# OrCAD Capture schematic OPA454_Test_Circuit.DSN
size A; title: OPA454 High-Voltage (100V), High-Current (50mA); rev: 1.1; note: Datasheet:SBOS391B EVM: N/A; note: Reference
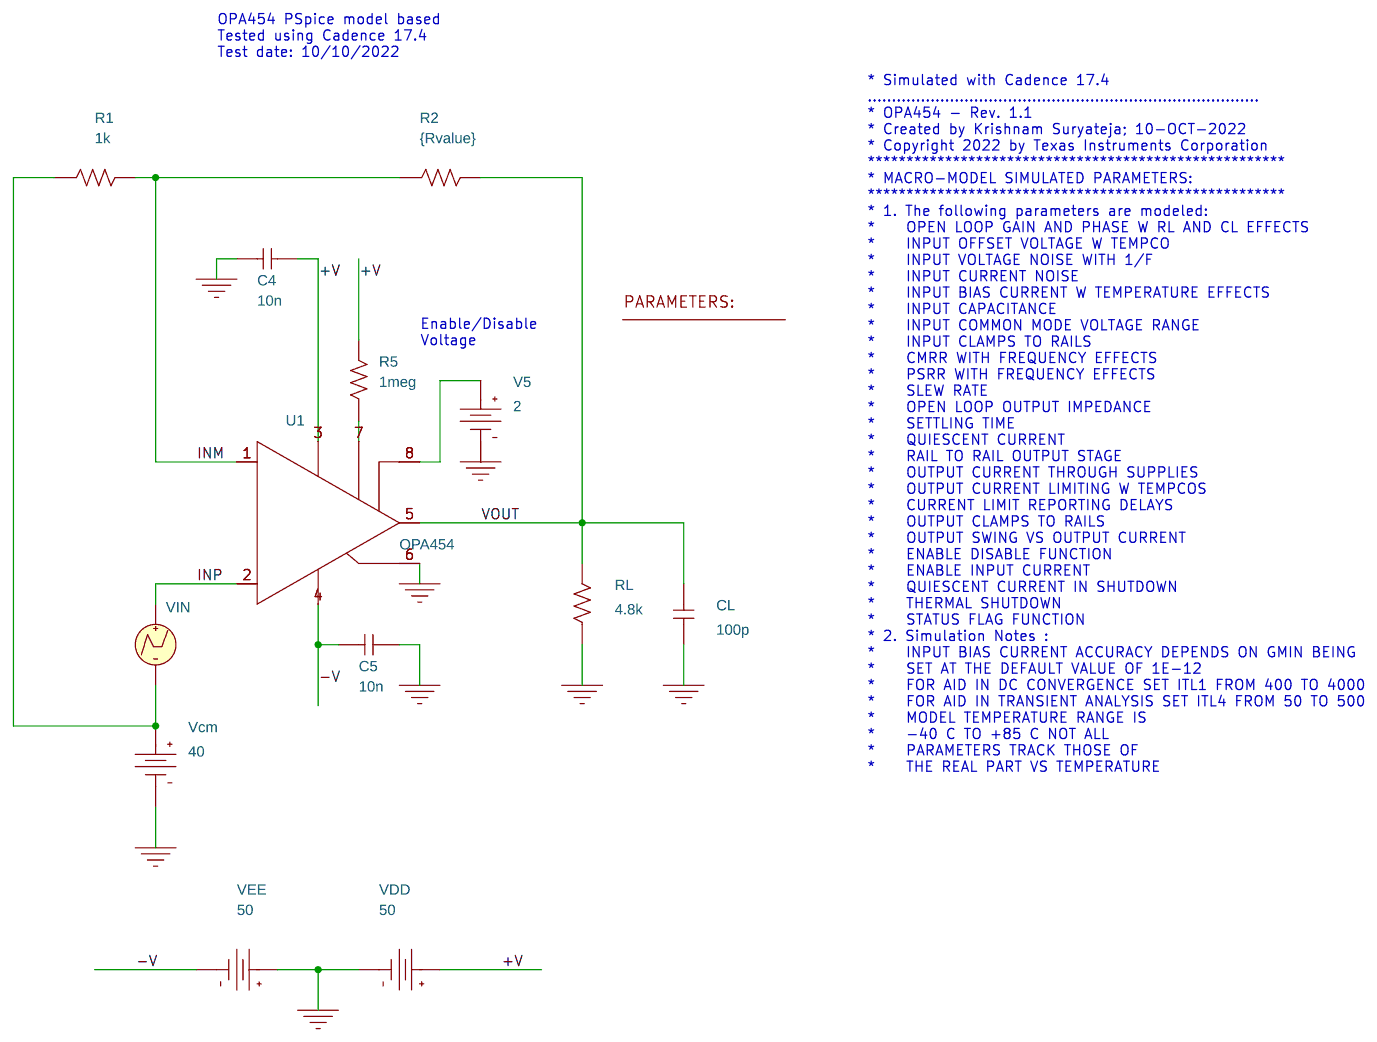
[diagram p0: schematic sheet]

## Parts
1  PARAM
C4  10n  [RAD/CK05]
C5  10n  [RAD/CK05]
CL  100p  [RAD/CK05]
R1  1k  [AX/RC05]
R2  {Rvalue}  [AX/RC05]
R5  1meg  [AX/RC05]
RL  4.8k  [AX/RC05]
U1  OPA454
V5  VDC
Vcm  VDC
VDD  VDC
VEE  VDC
VIN  VPWL

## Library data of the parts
1 = PARAM: Rvalue: 1k
C4 C5 CL = C
R1 R2 R5 RL = R
U1 = OPA454
V5 = VDC: DC: 2
Vcm = VDC: DC: 40
VDD VEE = VDC: DC: 50
VIN = VPWL: AC: 1; DC: 0; T1: 0; T2: 1n; T3: 10u; T4: 10.01u; T5: 20u; T6: 20.01u; T7: 30u; T8: 30.01u; V1: 0; V2: 0.5; V3: 0.5; V4: -0.5; V5: -0.5; V6: 0.5; V7: 0.5; V8: -0.5

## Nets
0: C4.1 C5.2 CL.1 RL.1 U1.6(E/DCom) V5.1(-) Vcm.1(-) VDD.1(-) VEE.0(+)
+V: C4.2 R5.2 U1.3(V+) VDD.0(+)
-V: C5.1 U1.4(V-) VEE.1(-)
INM: R1.2 R2.1 U1.1(-)
INP: U1.2(+) VIN.1(+)
VOUT: CL.2 R2.2 RL.2 U1.5(OUT)
N16771015: R1.1 Vcm.0(+) VIN.2(-)
N16798908: R5.1 U1.7(StatusFlg)
N16800499: U1.8(E/D) V5.0(+)

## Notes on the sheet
- OPA454 PSpice model based
  Tested using Cadence 17.4
  Test date: 10/10/2022
- * Simulated with Cadence 17.4
  .................................................................................
  * OPA454 - Rev. 1.1
  * Created by Krishnam Suryateja; 10-OCT-2022
  * Copyright 2022 by Texas Instruments Corporation
  ******************************************************
  * MACRO-MODEL SIMULATED PARAMETERS:
  ******************************************************
  * 1. The following parameters are modeled:
  *    OPEN LOOP GAIN AND PHASE W RL AND CL EFFECTS
  *    INPUT OFFSET VOLTAGE W TEMPCO
  *    INPUT VOLTAGE NOISE WITH 1/F
  *    INPUT CURRENT NOISE
  *    INPUT BIAS CURRENT W TEMPERATURE EFFECTS
  *    INPUT CAPACITANCE
  *    INPUT COMMON MODE VOLTAGE RANGE
  *    INPUT CLAMPS TO RAILS
  *    CMRR WITH FREQUENCY EFFECTS
  *    PSRR WITH FREQUENCY EFFECTS
  *    SLEW RATE
  *    OPEN LOOP OUTPUT IMPEDANCE
  *    SETTLING TIME
  *    QUIESCENT CURRENT
  *    RAIL TO RAIL OUTPUT STAGE
  *    OUTPUT CURRENT THROUGH SUPPLIES
  *    OUTPUT CURRENT LIMITING W TEMPCOS
  *    CURRENT LIMIT REPORTING DELAYS
  *    OUTPUT CLAMPS TO RAILS
  *    OUTPUT SWING VS OUTPUT CURRENT
  *    ENABLE DISABLE FUNCTION
  *    ENABLE INPUT CURRENT
  *    QUIESCENT CURRENT IN SHUTDOWN
  *    THERMAL SHUTDOWN
  *    STATUS FLAG FUNCTION
  * 2. Simulation Notes :
  *    INPUT BIAS CURRENT ACCURACY DEPENDS ON GMIN BEING
  *    SET AT THE DEFAULT VALUE OF 1E-12
  *    FOR AID IN DC CONVERGENCE SET ITL1 FROM 400 TO 4000
  *    FOR AID IN TRANSIENT ANALYSIS SET ITL4 FROM 50 TO 500
  *    MODEL TEMPERATURE RANGE IS
  *    -40 C TO +85 C NOT ALL
  *    PARAMETERS TRACK THOSE OF
  *    THE REAL PART VS TEMPERATURE
- Enable/Disable
  Voltage
